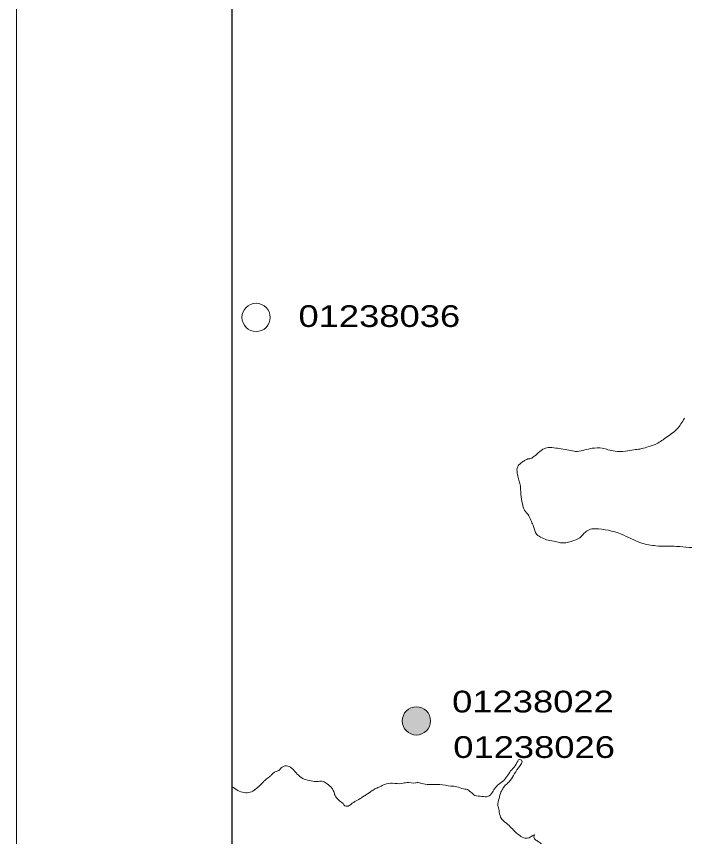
# Model space of a CAD drawing. Extents: x 854879 to 917879, y 8541948 to 8631048.
# Drawn here: x 854879 to 867173, y 8600845 to 8615947 of the extents above; entities that cross this region are included whole.
import ezdxf
from ezdxf.enums import TextEntityAlignment as Align

# ---------------------------------------------------------------- set-up
doc = ezdxf.new("R2010")
doc.units = 0
doc.header["$LTSCALE"] = 160
for name, color, linetype, lineweight in [('1', 7, 'Continuous', 13), ('12', 7, 'Continuous', 13), ('18', 7, 'Continuous', 13), ('3', 7, 'Continuous', 13), ('36', 7, 'Continuous', 13), ('44', 7, 'Continuous', 13), ('53', 7, 'Continuous', 13)]:
    doc.layers.add(name, color=color, linetype=linetype, lineweight=lineweight)

msp = doc.modelspace()

# ---------------------------------------------------------------- hatches: boundary and pattern name
at = {"layer": '1'}
msp.add_hatch(color=256, dxfattribs=at).paths.add_polyline_path([(862498.1, 8602975.5, 1), (861977.6, 8602975.5, 1)])

# ---------------------------------------------------------------- linework, layer by layer
for centre in [(859288.8, 8610404.5), (862237.9, 8602975.5)]:
    msp.add_circle(centre, 260.2, dxfattribs=at)
at = {"layer": '12'}
for points in [[(867170.9, 8608547.1), (867033.6, 8608352), (866823.5, 8608185.6), (866631.6, 8608065), (866481.1, 8608015.3), (866351, 8607980.8), (866241.5, 8607966.5), (866088.7, 8607939.8), (865892.8, 8607941.6), (865763.4, 8607968.2), (865656.8, 8607994.7), (865471.2, 8607993.8), (865336.1, 8607964.4), (865198.5, 8607937.6), (865079.1, 8607951.4), (864939.4, 8607975.6), (864802.3, 8607999.8), (864662.5, 8608006.2), (864563, 8607975.9), (864455.1, 8607886.6), (864401.1, 8607842.8), (864324.8, 8607800.1), (864309.6, 8607800.2), (864230.5, 8607770.4), (864166.5, 8607727.6), (864097.1, 8607649.2), (864093.5, 8607537)], [(864093.5, 8607537), (864115.3, 8607432.3), (864142.5, 8607345.4), (864160.9, 8607141.2), (864189.9, 8606972.7), (864226.9, 8606855.1), (864307.3, 8606752.4), (864354.6, 8606644.9), (864394.5, 8606555.3), (864449.1, 8606412), (864552.7, 8606347.3), (864661.7, 8606303), (864798.8, 8606276.3), (864892.7, 8606255), (864986.8, 8606254.2), (865086.2, 8606281.3), (865244.5, 8606346.2), (865347.2, 8606449.8), (865444.4, 8606505.1), (865525.8, 8606512), (866005.6, 8606413.3), (866383, 8606249.3), (866647, 8606198.5), (867025.9, 8606187.5), (867254.6, 8606170.1), (867824.9, 8606231.3), (868168.5, 8606256.3), (868269.6, 8606194.2), (868311.4, 8606038.3), (868257.9, 8605758.3), (868246.4, 8605623.3), (868247.5, 8605467.7), (868269.5, 8605370.6), (868311.2, 8605207.1), (868304.8, 8605064.4), (868257.8, 8604944.9), (868121.5, 8604783), (868082, 8604632.9), (868009.8, 8604536.7), (867912.6, 8604476.4), (867842.9, 8604364.8), (867818.6, 8604219.7), (867854.7, 8603995), (867904.7, 8603910.4), (867957.6, 8603851.3), (868043.6, 8603802.1), (868197.6, 8603678.3), (868235.5, 8603649.9), (868387.4, 8603584.8), (868443.2, 8603566.5), (868511.6, 8603532.7), (868579.2, 8603425.1), (868615.7, 8603246.2), (868632.3, 8603116.1), (868646.2, 8602970.6), (868650.1, 8602853.3), (868738.7, 8602538.9), (868808.5, 8602387.8), (868881.6, 8602315.8), (868990.6, 8602274), (869092.3, 8602275.7), (869145.8, 8602280.3), (869230, 8602310.1), (869339.6, 8602337.2), (869415.7, 8602321.2), (869514.8, 8602305), (869629.5, 8602332), (869718.8, 8602364.4), (869859.1, 8602409), (869971.3, 8602436.1), (870037.3, 8602425.3), (870072.5, 8602381.6), (870115, 8602307.3), (870147.1, 8602207.6), (870133.1, 8602062.4), (870154.5, 8601904.1), (870106.3, 8601649.6), (870072, 8601522.4), (870042.2, 8601326.3), (870081.2, 8601147.5), (870184.3, 8601029.3), (870293.3, 8600982.4), (870415.2, 8600971.1), (870565.3, 8600969.8), (870781.6, 8600985.7), (871049.2, 8601039.4), (871278.8, 8601113.8), (871416.9, 8601199.3), (871466.8, 8601364.6), (871490.7, 8601466.3), (871540.4, 8601616.3)]]:
    msp.add_spline(points, degree=3, dxfattribs=at)
at = {"layer": '18'}
msp.add_lwpolyline([(858846.4, 8601455.3), (858846.4, 8628560.7), (916445.6, 8628560.7), (916445.6, 8586757.5), (916451.2, 8586745.1)], dxfattribs=at)
for points in [[(863759.3, 8601328.2), (863739.7, 8601417.6), (863758.5, 8601547.4), (863795, 8601664.4), (863826, 8601722.8), (863874.8, 8601788.8), (863938.9, 8601849.5), (864026.3, 8601971.2), (864116.5, 8602113.4), (864173.5, 8602250.6), (864140.5, 8602263.6), (864076.3, 8602177.4), (863991.6, 8602076), (863847.6, 8601880.7), (863747.8, 8601802.4), (863691.4, 8601746.7), (863639.9, 8601660.4), (863555.3, 8601582), (863443.5, 8601585.3), (863316.5, 8601604), (863154.7, 8601717.3), (863106.4, 8601722.7), (862984.7, 8601761.8), (862872.9, 8601775.3), (862669.7, 8601804.7), (862438.3, 8601803.8), (862296.2, 8601832.8), (862250.5, 8601840.7), (862219.9, 8601833.3), (862062.3, 8601839.5), (861973.2, 8601822.2), (861800.3, 8601826), (861652.7, 8601806.6), (861565.9, 8601761.3), (861494.4, 8601731.2), (861425.5, 8601690.9), (861310.4, 8601612.7), (861249.1, 8601574.9), (861154.5, 8601514.4), (861054.9, 8601459), (861001.2, 8601416), (860922.3, 8601411.5), (860904.7, 8601429.4), (860892.2, 8601455)], [(860892.2, 8601455), (860741.3, 8601601), (860716.6, 8601675.1), (860681.6, 8601739.2), (860595.8, 8601813.9), (860519.9, 8601857.9), (860400.4, 8601859), (860265.8, 8601878), (860146.6, 8601917.3), (860045.6, 8601997.3), (859957.5, 8602089.9), (859874.1, 8602141.6), (859767.1, 8602124.7), (859705.5, 8602061.5), (859641.7, 8602039.2), (859598.1, 8602008.9), (859551.9, 8601960.9), (859475, 8601900.4), (859428.8, 8601857.5), (859277.5, 8601716.1), (859249.7, 8601694.6)], [(866438.8, 8596505.1), (866390.7, 8596533.4), (866332.4, 8596556.8), (866205.6, 8596603.5), (866099.2, 8596650.2), (865969.9, 8596702), (865873.9, 8596771.5), (865803.5, 8596868.8), (865811.7, 8596940.2), (865837.7, 8597013.9), (865902, 8597105.2), (865996.7, 8597181), (866050.3, 8597211.2), (865958.7, 8597206.8), (865920.4, 8597184.1), (865856.4, 8597133.6), (865795, 8597077.9), (865730.9, 8597014.6), (865662.8, 8597089), (865622.5, 8597135.2), (865549.1, 8597171.4), (865528.9, 8597191.9), (865478.1, 8597202.4), (865419.7, 8597207.9), (865356.1, 8597208.4), (865351.6, 8597282.3), (865375.2, 8597363.7), (865355.5, 8597440.3), (865280.1, 8597550.4), (865160.4, 8597658.9), (864963.9, 8597715.6), (864806.7, 8597781), (864706.2, 8597837.7), (864649.5, 8597873.4), (864629.7, 8597934.7), (864642.7, 8597970.3), (864653.1, 8598008.5), (864635.7, 8598057), (864644, 8598141.1), (864665.1, 8598230.2), (864734, 8598262.8), (864762.5, 8598334), (864771.3, 8598471.6), (864802.1, 8598514.7), (864762.3, 8598624.6), (864711.8, 8598673.3), (864706.8, 8598675.9), (864643.3, 8598691.7), (864617.9, 8598686.7), (864539.3, 8598715.3), (864541.9, 8598720.4), (864534.3, 8598725.5), (864529.2, 8598728.1), (864511.6, 8598753.7), (864484.2, 8598827.8), (864482.4, 8598912), (864490.3, 8598950.1), (864495.5, 8598965.4), (864460.2, 8599003.9), (864445.6, 8599083), (864446.3, 8599174.8), (864426.4, 8599225.9), (864416.8, 8599294.8), (864414.6, 8599335.6), (864430.4, 8599404.3), (864469, 8599460.1), (864540.6, 8599518.2), (864612.1, 8599555.9), (864658.2, 8599591.3), (864701.7, 8599629.2), (864760.8, 8599702.8), (864825.1, 8599794.1), (864861.3, 8599872.8), (864821.5, 8599975.1), (864740.7, 8600057.2), (864771.9, 8600138.6), (864793.2, 8600263.3), (864738.4, 8600396.2), (864650.8, 8600577.8), (864572.8, 8600675.2), (864494.5, 8600744.6), (864438.9, 8600780.6), (864401.2, 8600834.4), (864414.2, 8600875.1), (864312.1, 8600824.8), (864185, 8600835.9), (864023.3, 8600964.4), (863945.2, 8601046.6), (863841.6, 8601133.9), (863788.8, 8601203.1), (863759.3, 8601328.2)]]:
    msp.add_spline(points, degree=3, dxfattribs=at)
at = {"layer": '3'}
for points in [[(863759.3, 8601328.2), (863739.7, 8601417.6), (863758.5, 8601547.4), (863795, 8601664.4), (863826, 8601722.8), (863874.8, 8601788.8), (863938.9, 8601849.5), (864026.3, 8601971.2), (864116.5, 8602113.4), (864173.5, 8602250.6), (864140.5, 8602263.6), (864076.3, 8602177.4), (863991.6, 8602076), (863847.6, 8601880.7), (863747.8, 8601802.4), (863691.4, 8601746.7), (863639.9, 8601660.4), (863555.3, 8601582), (863443.5, 8601585.3), (863316.5, 8601604), (863154.7, 8601717.3), (863106.4, 8601722.7), (862984.7, 8601761.8), (862872.9, 8601775.3), (862669.7, 8601804.7), (862438.3, 8601803.8), (862296.2, 8601832.8), (862250.5, 8601840.7), (862219.9, 8601833.3), (862062.3, 8601839.5), (861973.2, 8601822.2), (861800.3, 8601826), (861652.7, 8601806.6), (861565.9, 8601761.3), (861494.4, 8601731.2), (861425.5, 8601690.9), (861310.4, 8601612.7), (861249.1, 8601574.9), (861154.5, 8601514.4), (861054.9, 8601459), (861001.2, 8601416), (860922.3, 8601411.5), (860904.7, 8601429.4), (860892.2, 8601455)], [(860892.2, 8601455), (860741.3, 8601601), (860716.6, 8601675.1), (860681.6, 8601739.2), (860595.8, 8601813.9), (860519.9, 8601857.9), (860400.4, 8601859), (860265.8, 8601878), (860146.6, 8601917.3), (860045.6, 8601997.3), (859957.5, 8602089.9), (859874.1, 8602141.6), (859767.1, 8602124.7), (859705.5, 8602061.5), (859641.7, 8602039.2), (859598.1, 8602008.9), (859551.9, 8601960.9), (859475, 8601900.4), (859428.8, 8601857.5), (859277.5, 8601716.1), (859177.7, 8601660.9), (859070.9, 8601654.2), (858951.7, 8601696.1), (858846.4, 8601764.2)], [(866438.8, 8596505.1), (866390.7, 8596533.4), (866332.4, 8596556.8), (866205.6, 8596603.5), (866099.2, 8596650.2), (865969.9, 8596702), (865873.9, 8596771.5), (865803.5, 8596868.8), (865811.7, 8596940.2), (865837.7, 8597013.9), (865902, 8597105.2), (865996.7, 8597181), (866050.3, 8597211.2), (865958.7, 8597206.8), (865920.4, 8597184.1), (865856.4, 8597133.6), (865795, 8597077.9), (865730.9, 8597014.6), (865662.8, 8597089), (865622.5, 8597135.2), (865549.1, 8597171.4), (865528.9, 8597191.9), (865478.1, 8597202.4), (865419.7, 8597207.9), (865356.1, 8597208.4), (865351.6, 8597282.3), (865375.2, 8597363.7), (865355.5, 8597440.3), (865280.1, 8597550.4), (865160.4, 8597658.9), (864963.9, 8597715.6), (864806.7, 8597781), (864706.2, 8597837.7), (864649.5, 8597873.4), (864629.7, 8597934.7), (864642.7, 8597970.3), (864653.1, 8598008.5), (864635.7, 8598057), (864644, 8598141.1), (864665.1, 8598230.2), (864734, 8598262.8), (864762.5, 8598334), (864771.3, 8598471.6), (864802.1, 8598514.7), (864762.3, 8598624.6), (864711.8, 8598673.3), (864706.8, 8598675.9), (864643.3, 8598691.7), (864617.9, 8598686.7), (864539.3, 8598715.3), (864541.9, 8598720.4), (864534.3, 8598725.5), (864529.2, 8598728.1), (864511.6, 8598753.7), (864484.2, 8598827.8), (864482.4, 8598912), (864490.3, 8598950.1), (864495.5, 8598965.4), (864460.2, 8599003.9), (864445.6, 8599083), (864446.3, 8599174.8), (864426.4, 8599225.9), (864416.8, 8599294.8), (864414.6, 8599335.6), (864430.4, 8599404.3), (864469, 8599460.1), (864540.6, 8599518.2), (864612.1, 8599555.9), (864658.2, 8599591.3), (864701.7, 8599629.2), (864760.8, 8599702.8), (864825.1, 8599794.1), (864861.3, 8599872.8), (864821.5, 8599975.1), (864740.7, 8600057.2), (864771.9, 8600138.6), (864793.2, 8600263.3), (864738.4, 8600396.2), (864650.8, 8600577.8), (864572.8, 8600675.2), (864494.5, 8600744.6), (864438.9, 8600780.6), (864401.2, 8600834.4), (864414.2, 8600875.1), (864312.1, 8600824.8), (864185, 8600835.9), (864023.3, 8600964.4), (863945.2, 8601046.6), (863841.6, 8601133.9), (863788.8, 8601203.1), (863759.3, 8601328.2)]]:
    msp.add_spline(points, degree=3, dxfattribs=at)
at = {"layer": '36'}
msp.add_lwpolyline([(854878.6, 8541948.4), (917878.6, 8541948.4), (917878.6, 8631048.4), (854878.6, 8631048.4)], close=True, dxfattribs=at)
at = {"layer": '36', "lineweight": 25}
msp.add_lwpolyline([(858846.4, 8628560.7), (916445.6, 8628560.7), (916445.6, 8544954.2), (858846.4, 8544954.2)], close=True, dxfattribs=at)
at = {"layer": '44'}
msp.add_lwpolyline([(858846.4, 8628560.7), (916445.6, 8628560.7), (916445.6, 8544954.2), (858846.4, 8544954.2)], close=True, dxfattribs=at)
at = {"layer": '53'}
for points in [[(867170.9, 8608547.1), (867033.6, 8608352), (866823.5, 8608185.6), (866631.6, 8608065), (866481.1, 8608015.3), (866351, 8607980.8), (866241.5, 8607966.5), (866088.7, 8607939.8), (865892.8, 8607941.6), (865763.4, 8607968.2), (865656.8, 8607994.7), (865471.2, 8607993.8), (865336.1, 8607964.4), (865198.5, 8607937.6), (865079.1, 8607951.4), (864939.4, 8607975.6), (864802.3, 8607999.8), (864662.5, 8608006.2), (864563, 8607975.9), (864455.1, 8607886.6), (864401.1, 8607842.8), (864324.8, 8607800.1), (864309.6, 8607800.2), (864230.5, 8607770.4), (864166.5, 8607727.6), (864097.1, 8607649.2), (864093.5, 8607537)], [(864093.5, 8607537), (864115.3, 8607432.3), (864142.5, 8607345.4), (864160.9, 8607141.2), (864189.9, 8606972.7), (864226.9, 8606855.1), (864307.3, 8606752.4), (864354.6, 8606644.9), (864394.5, 8606555.3), (864449.1, 8606412), (864552.7, 8606347.3), (864661.7, 8606303), (864798.8, 8606276.3), (864892.7, 8606255), (864986.8, 8606254.2), (865086.2, 8606281.3), (865244.5, 8606346.2), (865347.2, 8606449.8), (865444.4, 8606505.1), (865525.8, 8606512), (866005.6, 8606413.3), (866383, 8606249.3), (866647, 8606198.5), (867025.9, 8606187.5), (867254.6, 8606170.1), (867824.9, 8606231.3), (868168.5, 8606256.3), (868269.6, 8606194.2), (868311.4, 8606038.3), (868257.9, 8605758.3), (868246.4, 8605623.3), (868247.5, 8605467.7), (868269.5, 8605370.6), (868311.2, 8605207.1), (868304.8, 8605064.4), (868257.8, 8604944.9), (868121.5, 8604783), (868082, 8604632.9), (868009.8, 8604536.7), (867912.6, 8604476.4), (867842.9, 8604364.8), (867818.6, 8604219.7), (867854.7, 8603995), (867904.7, 8603910.4), (867957.6, 8603851.3), (868043.6, 8603802.1), (868197.6, 8603678.3), (868235.5, 8603649.9), (868387.4, 8603584.8), (868443.2, 8603566.5), (868511.6, 8603532.7), (868579.2, 8603425.1), (868615.7, 8603246.2), (868632.3, 8603116.1), (868646.2, 8602970.6), (868650.1, 8602853.3), (868738.7, 8602538.9), (868808.5, 8602387.8), (868881.6, 8602315.8), (868990.6, 8602274), (869092.3, 8602275.7), (869145.8, 8602280.3), (869230, 8602310.1), (869339.6, 8602337.2), (869415.7, 8602321.2), (869514.8, 8602305), (869629.5, 8602332), (869718.8, 8602364.4), (869859.1, 8602409), (869971.3, 8602436.1), (870037.3, 8602425.3), (870072.5, 8602381.6), (870115, 8602307.3), (870147.1, 8602207.6), (870133.1, 8602062.4), (870154.5, 8601904.1), (870106.3, 8601649.6), (870072, 8601522.4), (870042.2, 8601326.3), (870081.2, 8601147.5), (870184.3, 8601029.3), (870293.3, 8600982.4), (870415.2, 8600971.1), (870565.3, 8600969.8), (870781.6, 8600985.7), (871049.2, 8601039.4), (871278.8, 8601113.8), (871416.9, 8601199.3), (871466.8, 8601364.6), (871490.7, 8601466.3), (871540.4, 8601616.3)]]:
    msp.add_spline(points, degree=3, dxfattribs=at)

# ---------------------------------------------------------------- texts
at = {"layer": '1', "width": 1.25}
for s, p in [('01238036', (861556.2, 8610228.5)), ('01238022', (864383.4, 8603131.1)), ('01238026', (864404.1, 8602293.1))]:
    msp.add_text(s, height=400, dxfattribs=at).set_placement(p, align=Align.CENTER)

doc.saveas('drawing.dxf')
